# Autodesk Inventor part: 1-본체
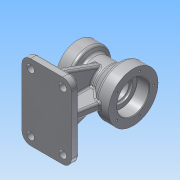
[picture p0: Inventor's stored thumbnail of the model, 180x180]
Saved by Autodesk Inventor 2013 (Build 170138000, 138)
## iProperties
Created: 2015-08
Part Number: 1-본체
Material: 알루미늄 6061
Document SubType Name: Modeling
Designer: Administrator
Density: 2.71 g/cm^3
Mass: 1062.79 g
Surface Area: 749.652 cm^2
Volume: 392.172 cm^3
Author: Administrator
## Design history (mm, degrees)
sketch "스케치1"
  geometry: L1 (-45, 0)-(45, 0); L2 (-45, 0)-(-45, 35); L3 (-45, 35)-(-25, 35); L4 (-25, 35)-(-19.804, 26); L5 (-19.804, 26)-(8.315, 26); L6 (8.315, 26)-(25, 40); L7 (25, 40)-(45, 40); L8 (45, 40)-(45, 0); 2 further points
  constraints: 16 end point, 3 parallel, 2 perpendicular, 1 coincident, 1 horizontal, 1 midpoint
  dimensions: "d0" = 90 distance of L1.start L1.end; "d1" = 70 diameter of L3 L1; "d2" = 80 diameter of L7 L1; "d3" = 52 diameter of L5 L1; "d4" = 60 deg angle of L5 L4; "d5" = 40 deg angle of L5 L6; "d6" = 20 distance of L2.end L3.end; "d7" = 20 distance of L6.end L7.end
revolve "회전1" sketch "스케치1" stored, may be unused: angle "d8" = 90 deg
node "작업 평면1"
sketch "스케치4"
  geometry: L1 (35, -78)-(-45, -78); L2 (-45, -78)-(-45, -90); L3 (-45, -90)-(35, -90); L4 (35, -90)-(35, -78); L5 (35, -78)-(-45, -90); L6 (-45, -78)-(35, -90); L7 (-45, -35)-(-45, 35) reference; L8 (-45, 35)-(-25, 35) reference; L9 (-25, 35)-(-19.804, 26) reference; L10 (-19.804, 26)-(8.315, 26) reference; L11 (8.315, 26)-(25, 40) reference; L12 (25, 40)-(45, 40) reference; L13 (45, 40)-(45, -40) reference; L14 (45, -40)-(25, -40) reference; L15 (25, -40)-(8.315, -26) reference; L16 (8.315, -26)-(-19.804, -26) reference; L17 (-19.804, -26)-(-25, -35) reference; L18 (-25, -35)-(-45, -35) reference; 2 further points
  constraints: 12 end point, 2 midpoint, 2 parallel, 1 horizontal, 1 perpendicular, 1 vertical alignment
  dimensions: "d14" = 12 distance of L1.end L2.end; "d16" = 80 distance of L2.end L3.end; "d17" = 90 distance from line of L3 point (0, 0)
extrude "돌출2" join sketch "스케치4" stored distance "d18" = 122; taper "d19" = 0 deg
node "작업 평면2"
sketch "스케치7"
  geometry: L1 (-122, 0)-(-122, 12) reference; L2 (-122, 12)-(0, 12) reference; L3 (0, 12)-(0, 0) reference; L4 (0, 0)-(-122, 0) reference; L5 (-10, 12)-(-35.909, 83.185); L6 (-112, 12)-(-86.091, 83.185); A1 r 26 centre (-61, 90) between (-35.909, 83.185) and (-86.091, 83.185) reference; 1 further point
  constraints: 4 end point, 2 point on circle, 2 point on line, 1 equal length
  dimensions: "d20" = 10 distance of L1.end L6.start; "d21" = 10 distance of L2.end L5.start; "d22" = 70 deg angle of L2 L6
extrude "돌출3" join sketch "스케치7" stored distance "d23" = 12; taper "d24" = 0 deg
sketch "스케치10"
  geometry: L1 (-45, -35)-(-45, 35) reference; L2 (-45, 35)-(-25, 35) reference; L3 (-25, 35)-(-19.804, 26) reference; L4 (-19.804, 26)-(8.315, 26) reference; L5 (8.315, 26)-(25, 40) reference; L6 (25, 40)-(45, 40) reference; L7 (45, 40)-(45, -40) reference; L8 (45, -40)-(25, -40) reference; L9 (25, -40)-(8.315, -26) reference; L10 (8.315, -26)-(1, -26) reference; L11 (1, -26)-(1, -78) reference; L12 (1, -78)-(35, -78) reference; L13 (35, -78)-(35, -90) reference; L14 (35, -90)-(-45, -90) reference; L15 (-45, -90)-(-45, -78) reference; L16 (-45, -78)-(-11, -78) reference; L17 (-11, -78)-(-11, -26) reference; L18 (-11, -26)-(-19.804, -26) reference; L19 (-19.804, -26)-(-25, -35) reference; L20 (-25, -35)-(-45, -35) reference; L21 (-35, -78)-(-35, -8.917); L22 (-35, -8.917)-(37.181, -8.917); L23 (37.181, -8.917)-(25, -78); 1 further point
  constraints: 6 end point, 2 perpendicular, 2 point on line
  dimensions: "d30" = 10 distance from line of L21.start L15; "d32" = 10 distance from line of L13 L23.end; "d33" = 80 deg angle of L12 L23
extrude "돌출5" join sketch "스케치10" stored distance "d34" = 12; taper "d35" = 0 deg
fillet "모깎기1" dims "d36" = 14
hole "구멍1" diameter "d39" = 38; stored, may be unused: countersink angle "d43" = 90 deg, drill point angle "d45" = 0 deg; dims "d37" = 10, "d38" = 10, "d40" = 6, "d41" = 52, "d42" = 20, "d44" = 23
fillet "모깎기2" dims "d46" = 3
hole "구멍2" diameter "d49" = 32; stored, may be unused: countersink angle "d53" = 90 deg, drill point angle "d55" = 0 deg; dims "d47" = 10, "d48" = 10, "d50" = 6, "d51" = 40, "d52" = 17, "d54" = 23
fillet "모깎기3" dims "d56" = 5, "d57" = 5
fillet "모깎기4" dims "d58" = 0.3
fillet "모깎기5" dims "d59" = 0.3
sketch "스케치13"
  geometry: C1 r 26 at (0, 0) reference; 1 further point
  constraints: 1 vertical alignment
  dimensions: "d60" = 33 distance of point (0, 33) C1.centre
hole "구멍3" sketch "스케치13" at (0, 33) diameter "d61" = 3.242; stored, may be unused: countersink angle "d65" = 90 deg, drill point angle "d67" = 118 deg; dims "d62" = 10, "d63" = 40, "d64" = 17, "d66" = 13
sketch "스케치14"
  geometry: C1 r 20 at (0, 0) reference; 1 further point
  constraints: 1 vertical alignment
  dimensions: "d71" = 27 distance of C1.centre point (0, 27)
hole "구멍4" sketch "스케치14" at (0, 27) diameter "d72" = 3.242; stored, may be unused: countersink angle "d76" = 90 deg, drill point angle "d78" = 118 deg; dims "d73" = 10, "d74" = 40, "d75" = 17, "d77" = 13
sketch "스케치15"
  geometry: C1 r 6 at (0, 14); C2 r 6 at (52, 14); C3 r 6 at (52, 108); C4 r 6 at (0, 108); A1 r 14 centre (0, 108) between (0, 122) and (-14, 108) reference; A2 r 14 centre (0, 14) between (-14, 14) and (0, 0) reference; A3 r 14 centre (52, 14) between (52, 0) and (66, 14) reference; A4 r 14 centre (52, 108) between (66, 108) and (52, 122) reference; 1 further point
  constraints: 4 centre point, 4 coincident
  dimensions: "d82" = 12 diameter of C1; "d83" = 12 diameter of C2; "d84" = 12 diameter of C3; "d85" = 12 diameter of C4
extrude "돌출6" cut sketch "스케치15" stored distance "d86" = 12; taper "d87" = 0 deg
sketch "스케치16"
  geometry: L1 (31, 36)-(31, 30); L2 (43, 36)-(43, 30); L3 (0, 12)-(14, 12) reference; A1 r 26 centre (61, 90) between (35.909, 83.185) and (55, 64.702) reference; A2 r 6 centre (37, 36) between (43, 36) and (31, 36); A3 r 6 centre (37, 30) between (31, 30) and (43, 30)
  constraints: 4 end point, 4 point on circle, 4 tangent, 2 centre point, 1 vertical alignment
  dimensions: "d88" = 12 diameter of A2; "d89" = 12 diameter of A3; "d90" = 18 dimension on A3 A2; "d91" = 24 horizontal distance of A1.centre A2.centre; "d92" = 18 distance from line of L3 A3.centre
extrude "돌출7" cut sketch "스케치16" stored distance "d93" = 12; taper "d94" = 0 deg
fillet "모깎기6" dims "d95" = 3
fillet "모깎기7" dims "d96" = 3
fillet "모깎기8" dims "d97" = 3
fillet "모깎기9" dims "d98" = 3
chamfer "모따기1" distance "d99" = 1; stored, may be unused: second distance "d100" = 2, angle "d101" = 45 deg
fillet "모깎기10" dims "d102" = 3
sketch "스케치18"
  geometry: L1 (-42, -78)-(-31, -78) reference; L2 (-35, -37.881)-(-35, -75) reference; 2 further points
  constraints: 1 other
  dimensions: "d105" = 24 distance from line of point (-19, -54) L1; "d106" = 16 distance from line of point (-19, -54) L2
feature "엠보싱1" sketch "스케치18" dims "d0" = 90, "d1" = 70, "d2" = 80, "d3" = 52, "d4" = 60 deg, "d5" = 40 deg, "d6" = 20, "d7" = 20, "d107" = 0.5, "d108" = 0
sketch "스케치19"
  geometry: 1 further point
sketch "스케치20"
  geometry: 1 further point
node "솔리드1"
pattern_circular "원형 패턴1" dims angle "d69" = 360 deg
pattern_circular "원형 패턴2" dims angle "d80" = 360 deg
mirror "대칭1"
node "절단 모서리 투영1"
node "절단 모서리 투영2"
node "절단 모서리 투영4"
